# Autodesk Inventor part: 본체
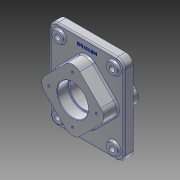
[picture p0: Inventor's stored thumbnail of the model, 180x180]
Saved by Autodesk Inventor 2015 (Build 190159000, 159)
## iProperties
Created: 2026-07
Part Number: 본체
Material: 알루미늄 6061
Document SubType Name: Modeling
Designer: USER
Density: 2.7 g/cm^3
Appearance: 알루미늄 - 평지
Mass: 2145.45 g
Surface Area: 949.899 cm^2
Volume: 794.611 cm^3
Author: USER
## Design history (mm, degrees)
sketch "스케치2"
  geometry: L1 (75, 90)-(-75, 90); L2 (-75, 90)-(-75, -90); L3 (-75, -90)-(75, -90); L4 (75, -90)-(75, 90); L5 (75, 90)-(-75, -90); L6 (-75, 90)-(75, -90); 1 further point
  constraints: 12 end point, 2 midpoint, 2 parallel, 1 horizontal, 1 perpendicular
  dimensions: "d4" = 150 distance of L3.end L2.end; "d5" = 180 distance of L2.end L1.end
extrude "돌출1" new body sketch "스케치2" stored distance "d6" = 18; taper "d7" = 0 deg
sketch "스케치3"
  geometry: 1 further point
sketch "스케치5"
  geometry: L1 (-75, -90)-(-75, 90) reference; L2 (-75, 90)-(75, 90) reference; L3 (75, 90)-(75, -90) reference; L4 (75, -90)-(-75, -90) reference; L5 (-56.569, -14.142)-(-14.142, -56.569); L6 (14.142, -56.569)-(56.569, -14.142); L7 (56.569, 14.142)-(14.142, 56.569); L8 (-14.142, 56.569)-(-56.569, 14.142); L9 (-70.711, 0)-(70.711, 0); L10 (0, -70.711)-(0, 70.711); A1 r 20 centre (0, 42.426) between (14.142, 56.569) and (-14.142, 56.569); A2 r 20 centre (-42.426, 0) between (-56.569, 14.142) and (-56.569, -14.142); A3 r 20 centre (42.426, 0) between (56.569, -14.142) and (56.569, 14.142); A4 r 20 centre (0, -42.426) between (-14.142, -56.569) and (14.142, -56.569); 2 further points
  constraints: 12 end point, 8 point on circle, 8 point on line, 8 tangent, 4 centre point, 3 equal radius, 3 midpoint, 2 parallel, 1 horizontal alignment, 1 perpendicular
  dimensions: "d15" = 100 distance of L9.start L10.start; "d16" = 100 distance of L10.start L9.end; "d17" = 20 radius of A1
extrude "돌출3" join sketch "스케치5" distance "d18" = 29; taper "d20" = 0 deg; dims "d19" = 41, "d21" = 0
fillet "모깎기1" dims "d22" = 15
sketch "스케치9"
  geometry: 1 further point
hole "구멍2" sketch "스케치9" at (0, 0) diameter "d35" = 54; stored, may be unused: countersink angle "d39" = 90 deg, drill point angle "d41" = 0 deg; dims "d36" = 6, "d37" = 62, "d38" = 22, "d40" = 8
sketch "스케치10"
  geometry: L1 (60, -90)-(-60, -90) reference; L2 (-75, -75)-(-75, 75) reference; L3 (-60, 90)-(60, 90) reference; L4 (75, 75)-(75, -75) reference; L5 (-14.142, -56.569)-(-56.569, -14.142) reference; L6 (-56.569, 14.142)-(-14.142, 56.569) reference; L7 (14.142, 56.569)-(56.569, 14.142) reference; L8 (56.569, -14.142)-(14.142, -56.569) reference; C1 r 27 at (0, 0) reference; C2 r 11 at (-55, 70); A1 r 15 centre (60, -75) between (60, -90) and (75, -75) reference; A2 r 15 centre (-60, -75) between (-75, -75) and (-60, -90) reference; A3 r 15 centre (-60, 75) between (-60, 90) and (-75, 75) reference; A4 r 15 centre (60, 75) between (75, 75) and (60, 90) reference; A5 r 20 centre (-42.426, 0) between (-56.569, 14.142) and (-56.569, -14.142) reference; A6 r 20 centre (0, 42.426) between (14.142, 56.569) and (-14.142, 56.569) reference; A7 r 20 centre (42.426, 0) between (56.569, -14.142) and (56.569, 14.142) reference; A8 r 20 centre (0, -42.426) between (-14.142, -56.569) and (14.142, -56.569) reference; 1 further point
  constraints: 1 centre point
  dimensions: "d42" = 22 diameter of C2; "d43" = 55 horizontal distance of C2.centre point (0, 0); "d44" = 70 vertical distance of C2.centre point (0, 0)
extrude "돌출5" join sketch "스케치10" distance "d45" = 5; taper "d46" = 0 deg
hole "구멍3" diameter "d49" = 11; stored, may be unused: countersink angle "d53" = 90 deg, drill point angle "d55" = 0 deg; dims "d47" = 10, "d48" = 10, "d50" = 6, "d51" = 62, "d52" = 22, "d54" = 8
sketch "스케치11"
  geometry: L1 (-14.142, -56.569)-(-56.569, -14.142) reference; L2 (-56.569, 14.142)-(-14.142, 56.569) reference; L3 (14.142, 56.569)-(56.569, 14.142) reference; L4 (56.569, -14.142)-(14.142, -56.569) reference; L5 (56.569, -14.142)-(14.142, -56.569) reference; L6 (-14.142, -56.569)-(-56.569, -14.142) reference; L7 (-56.569, 14.142)-(-14.142, 56.569) reference; L8 (14.142, 56.569)-(56.569, 14.142) reference; L9 (-60, -90)-(60, -90) reference; L10 (75, -75)-(75, 75) reference; L11 (60, 90)-(-60, 90) reference; L12 (-75, 75)-(-75, -75) reference; L13 (0, 0)-(0, 48); C1 r 31 at (0, 0) reference; C2 r 27 at (0, 0) reference; C3 r 48 at (0, 0); C4 r 11 at (55, -70) reference; C5 r 11 at (-55, -70) reference; C6 r 11 at (55, 70) reference; C7 r 11 at (-55, 70) reference; A1 r 20 centre (-42.426, 0) between (-56.569, 14.142) and (-56.569, -14.142) reference; A2 r 20 centre (0, 42.426) between (14.142, 56.569) and (-14.142, 56.569) reference; A3 r 20 centre (42.426, 0) between (56.569, -14.142) and (56.569, 14.142) reference; A4 r 20 centre (0, -42.426) between (-14.142, -56.569) and (14.142, -56.569) reference; A5 r 20 centre (42.426, 0) between (56.569, -14.142) and (56.569, 14.142) reference; A6 r 20 centre (0, -42.426) between (-14.142, -56.569) and (14.142, -56.569) reference; A7 r 20 centre (-42.426, 0) between (-56.569, 14.142) and (-56.569, -14.142) reference; A8 r 20 centre (0, 42.426) between (14.142, 56.569) and (-14.142, 56.569) reference; A9 r 15 centre (-60, -75) between (-75, -75) and (-60, -90) reference; A10 r 15 centre (60, -75) between (60, -90) and (75, -75) reference; A11 r 15 centre (60, 75) between (75, 75) and (60, 90) reference; A12 r 15 centre (-60, 75) between (-60, 90) and (-75, 75) reference; 1 further point
  constraints: 2 end point, 1 centre point, 1 coincident, 1 vertical
  dimensions: "d56" = 96 diameter of C3; "d57" = 48 distance of L13.start L13.end
hole "구멍4" sketch "스케치11" at (0, 48) diameter "d58" = 4.917; stored, may be unused: countersink angle "d62" = 90 deg, drill point angle "d64" = 118 deg; dims "d59" = 10, "d60" = 62, "d61" = 22, "d63" = 13
sketch "스케치12"
  geometry: L1 (60, 90)-(-60, 90) reference; 2 further points
  constraints: 1 vertical alignment, 1 other
  dimensions: "d68" = 15 distance from line of point (0, 75) L1
feature "엠보싱1" sketch "스케치12" dims "d4" = 150, "d5" = 180, "d15" = 100, "d16" = 100, "d17" = 20, "d69" = 0.5, "d70" = 0
chamfer "모따기1" distance "d71" = 1; stored, may be unused: second distance "d72" = 2, angle "d73" = 45 deg
fillet "모깎기2" dims "d74" = 1
fillet "모깎기3" dims "d75" = 3
fillet "모깎기4" dims "d76" = 3
sketch "스케치13"
  geometry: L1 (0, 0)-(0, -48)
  constraints: 2 end point, 1 vertical
  dimensions: "d77" = 48 distance of L1.start L1.end
hole "구멍5" sketch "스케치13" at (0, -48) diameter "d78" = 4.917; stored, may be unused: countersink angle "d82" = 90 deg, drill point angle "d84" = 118 deg; dims "d79" = 10, "d80" = 4, "d81" = 2, "d83" = 13
sketch "스케치14"
  geometry: 2 further points
  constraints: 1 coincident
hole "구멍6" sketch "스케치14" at (0, 0) diameter "d88" = 62; stored, may be unused: countersink angle "d92" = 90 deg, drill point angle "d94" = 0 deg; dims "d89" = 12, "d90" = 4, "d91" = 2, "d93" = 22
fillet "모깎기5" dims "d95" = 1
chamfer "모따기2" distance "d96" = 1; stored, may be unused: second distance "d97" = 2, angle "d98" = 45 deg
node "솔리드1"
mirror "대칭4"
mirror "대칭5"
pattern_circular "원형 패턴1" dims angle "d66" = 360 deg
pattern_circular "원형 패턴3" dims angle "d100" = 360 deg
node "투영된 루프3"
node "절단 모서리 투영2"
node "절단 모서리 투영4"
node "절단 모서리 투영5"
